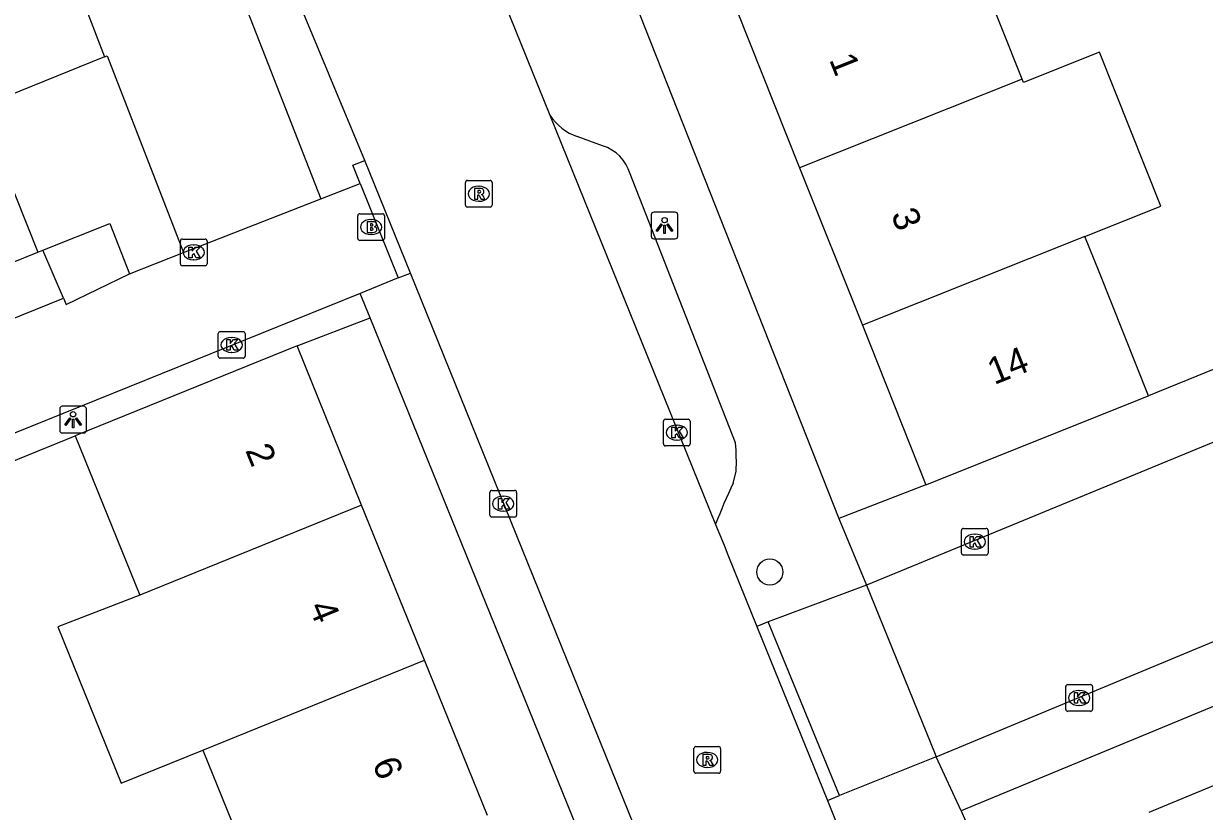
# Model space of a CAD drawing. Extents: x 162990 to 165007, y 383433 to 384336.
# Drawn here: x 163858.48 to 163902.75, y 383900.1 to 383929.63 of the extents above; entities that cross this region are included whole.
import ezdxf

# ---------------------------------------------------------------- set-up
doc = ezdxf.new("R2010")
doc.units = 0
for name, color, linetype in [('IMGEO_Boom', 7, 'Continuous'), ('IMGEO_Brandkraan', 7, 'Continuous'), ('IMGEO_Kolk', 7, 'Continuous'), ('IMGEO_Lichtpunt', 7, 'Continuous'), ('IMGEO_Pand', 7, 'Continuous'), ('IMGEO_Pand_nummerreeks', 7, 'Continuous'), ('IMGEO_Rijbaan_lokaal_open', 7, 'Continuous'), ('IMGEO_Rioolput', 7, 'Continuous'), ('IMGEO_Voetpad_open', 7, 'Continuous')]:
    doc.layers.add(name, color=color, linetype=linetype)

msp = doc.modelspace()

# ---------------------------------------------------------------- linework, layer by layer
at = {"layer": 'IMGEO_Boom'}
msp.add_circle((163886.457, 383909.07), 0.489, dxfattribs=at)
at = {"layer": 'IMGEO_Brandkraan'}
for p, q in [((163871.01, 383921.575), (163871.01, 383922.427)), ((163871.085, 383922.501), (163871.937, 383922.501)), ((163871.498, 383922.281), (163871.523, 383922.281)), ((163872.011, 383922.427), (163872.011, 383921.575)), ((163871.521, 383921.721), (163871.496, 383921.721)), ((163871.937, 383921.501), (163871.085, 383921.501))]:
    msp.add_line(p, q, dxfattribs=at)
for points in [[(163871.01, 383921.575), (163871.01, 383922.427)], [(163871.085, 383922.501), (163871.937, 383922.501)], [(163871.358, 383922.201), (163871.358, 383921.801), (163871.571, 383921.801)], [(163871.589, 383922.201), (163871.358, 383922.201)], [(163872.011, 383922.427), (163872.011, 383921.575)], [(163871.537, 383922.12), (163871.483, 383922.12), (163871.483, 383922.044)], [(163871.483, 383922.044), (163871.536, 383922.044)], [(163871.545, 383921.968), (163871.483, 383921.968), (163871.483, 383921.887)], [(163871.483, 383921.887), (163871.545, 383921.887)], [(163871.937, 383921.501), (163871.085, 383921.501)]]:
    msp.add_lwpolyline(points, dxfattribs=at)
for centre, radius, start, end in [((163871.087, 383922.425), 0.0765, 91.552, 178.448), ((163871.087, 383922.425), 0.0765, 91.552, 178.448), ((163871.593, 383922.056), 0.145, 59.4692, 91.5367), ((163871.618, 383922.103), 0.0922, 285.5137, 58.1501), ((163871.935, 383922.425), 0.0765, 1.552, 88.448), ((163871.935, 383922.425), 0.0765, 1.552, 88.448), ((163871.538, 383922.082), 0.0379, 267.8285, 90.9355), ((163871.546, 383921.927), 0.0404, 269.8759, 90.5077), ((163871.577, 383922.052), 0.251, 268.6676, 293.5347), ((163871.623, 383921.911), 0.105, 301.3115, 78.989), ((163871.087, 383921.577), 0.0765, 181.552, 268.448), ((163871.087, 383921.577), 0.0765, 181.552, 268.448), ((163871.935, 383921.577), 0.0765, 271.552, 358.448), ((163871.935, 383921.577), 0.0765, 271.552, 358.448)]:
    msp.add_arc(centre, radius, start, end, dxfattribs=at)
for centre, major_axis, ratio, start_param, end_param in [((163871.497, 383922.001), (-0.387, 0.002), 0.722429, 4.712389, 7.853982), ((163871.522, 383922.001), (-0.39, 0.002), 0.717154, 1.570796, 4.712389)]:
    msp.add_ellipse(centre, major_axis=major_axis, ratio=ratio, start_param=start_param, end_param=end_param, dxfattribs=at)
at = {"layer": 'IMGEO_Kolk'}
for p, q in [((163864.359, 383920.625), (163864.359, 383921.477)), ((163864.434, 383921.551), (163865.286, 383921.551)), ((163864.847, 383921.331), (163864.872, 383921.331)), ((163865.36, 383921.477), (163865.36, 383920.625)), ((163865.286, 383920.551), (163864.434, 383920.551)), ((163864.87, 383920.771), (163864.845, 383920.771)), ((163865.782, 383917.158), (163865.782, 383918.01)), ((163865.857, 383918.084), (163866.709, 383918.084)), ((163866.27, 383917.864), (163866.295, 383917.864)), ((163866.783, 383918.01), (163866.783, 383917.158)), ((163866.293, 383917.304), (163866.268, 383917.304)), ((163866.709, 383917.084), (163865.857, 383917.084)), ((163882.468, 383913.872), (163882.468, 383914.724)), ((163882.543, 383914.798), (163883.395, 383914.798)), ((163883.469, 383914.724), (163883.469, 383913.872)), ((163882.956, 383914.578), (163882.981, 383914.578)), ((163883.395, 383913.798), (163882.543, 383913.798)), ((163882.979, 383914.018), (163882.954, 383914.018)), ((163875.963, 383911.203), (163875.963, 383912.055)), ((163876.038, 383912.129), (163876.89, 383912.129)), ((163876.964, 383912.055), (163876.964, 383911.203)), ((163876.451, 383911.909), (163876.476, 383911.909)), ((163876.89, 383911.129), (163876.038, 383911.129)), ((163876.474, 383911.349), (163876.449, 383911.349)), ((163893.64, 383909.779), (163893.64, 383910.631)), ((163893.715, 383910.705), (163894.567, 383910.705)), ((163894.641, 383910.631), (163894.641, 383909.779)), ((163894.128, 383910.485), (163894.153, 383910.485)), ((163894.151, 383909.925), (163894.126, 383909.925)), ((163894.567, 383909.705), (163893.715, 383909.705)), ((163897.552, 383903.921), (163897.552, 383904.773)), ((163897.627, 383904.847), (163898.479, 383904.847)), ((163898.04, 383904.627), (163898.065, 383904.627)), ((163898.553, 383904.773), (163898.553, 383903.921)), ((163898.063, 383904.067), (163898.038, 383904.067)), ((163898.479, 383903.847), (163897.627, 383903.847))]:
    msp.add_line(p, q, dxfattribs=at)
for points in [[(163864.359, 383920.625), (163864.359, 383921.477)], [(163864.434, 383921.551), (163865.286, 383921.551)], [(163864.68, 383921.251), (163864.803, 383921.251), (163864.803, 383921.1), (163864.933, 383921.251), (163865.097, 383921.251), (163864.951, 383921.1), (163865.104, 383920.851), (163864.952, 383920.851), (163864.867, 383921.015), (163864.803, 383920.948), (163864.803, 383920.851), (163864.68, 383920.851), (163864.68, 383921.251)], [(163865.36, 383921.477), (163865.36, 383920.625)], [(163865.286, 383920.551), (163864.434, 383920.551)], [(163865.782, 383917.158), (163865.782, 383918.01)], [(163865.857, 383918.084), (163866.709, 383918.084)], [(163866.103, 383917.784), (163866.226, 383917.784), (163866.226, 383917.633), (163866.356, 383917.784), (163866.52, 383917.784), (163866.374, 383917.633), (163866.527, 383917.384), (163866.375, 383917.384), (163866.29, 383917.548), (163866.226, 383917.481), (163866.226, 383917.384), (163866.103, 383917.384), (163866.103, 383917.784)], [(163866.783, 383918.01), (163866.783, 383917.158)], [(163866.709, 383917.084), (163865.857, 383917.084)], [(163882.468, 383913.872), (163882.468, 383914.724)], [(163882.543, 383914.798), (163883.395, 383914.798)], [(163883.469, 383914.724), (163883.469, 383913.872)], [(163882.789, 383914.498), (163882.912, 383914.498), (163882.912, 383914.347), (163883.042, 383914.498), (163883.206, 383914.498), (163883.06, 383914.347), (163883.213, 383914.098), (163883.061, 383914.098), (163882.976, 383914.262), (163882.912, 383914.195), (163882.912, 383914.098), (163882.789, 383914.098), (163882.789, 383914.498)], [(163883.395, 383913.798), (163882.543, 383913.798)], [(163875.963, 383911.203), (163875.963, 383912.055)], [(163876.038, 383912.129), (163876.89, 383912.129)], [(163876.964, 383912.055), (163876.964, 383911.203)], [(163876.284, 383911.829), (163876.407, 383911.829), (163876.407, 383911.678), (163876.537, 383911.829), (163876.701, 383911.829), (163876.555, 383911.678), (163876.708, 383911.429), (163876.556, 383911.429), (163876.471, 383911.593), (163876.407, 383911.526), (163876.407, 383911.429), (163876.284, 383911.429), (163876.284, 383911.829)], [(163876.89, 383911.129), (163876.038, 383911.129)], [(163893.64, 383909.779), (163893.64, 383910.631)], [(163893.715, 383910.705), (163894.567, 383910.705)], [(163894.641, 383910.631), (163894.641, 383909.779)], [(163893.961, 383910.405), (163894.084, 383910.405), (163894.084, 383910.254), (163894.214, 383910.405), (163894.378, 383910.405), (163894.232, 383910.254), (163894.385, 383910.005), (163894.233, 383910.005), (163894.148, 383910.169), (163894.084, 383910.102), (163894.084, 383910.005), (163893.961, 383910.005), (163893.961, 383910.405)], [(163894.567, 383909.705), (163893.715, 383909.705)], [(163897.552, 383903.921), (163897.552, 383904.773)], [(163897.627, 383904.847), (163898.479, 383904.847)], [(163897.873, 383904.547), (163897.996, 383904.547), (163897.996, 383904.396), (163898.126, 383904.547), (163898.29, 383904.547), (163898.144, 383904.396), (163898.297, 383904.147), (163898.145, 383904.147), (163898.06, 383904.311), (163897.996, 383904.244), (163897.996, 383904.147), (163897.873, 383904.147), (163897.873, 383904.547)], [(163898.553, 383904.773), (163898.553, 383903.921)], [(163898.479, 383903.847), (163897.627, 383903.847)]]:
    msp.add_lwpolyline(points, dxfattribs=at)
for centre, start, end in [((163864.436, 383921.475), 91.552, 178.448), ((163864.436, 383921.475), 91.552, 178.448), ((163865.284, 383921.475), 1.552, 88.448), ((163865.284, 383921.475), 1.552, 88.448), ((163864.436, 383920.627), 181.552, 268.448), ((163864.436, 383920.627), 181.552, 268.448), ((163865.284, 383920.627), 271.552, 358.448), ((163865.284, 383920.627), 271.552, 358.448), ((163865.859, 383918.008), 91.552, 178.448), ((163865.859, 383918.008), 91.552, 178.448), ((163866.707, 383918.008), 1.552, 88.448), ((163866.707, 383918.008), 1.552, 88.448), ((163865.859, 383917.16), 181.552, 268.448), ((163865.859, 383917.16), 181.552, 268.448), ((163866.707, 383917.16), 271.552, 358.448), ((163866.707, 383917.16), 271.552, 358.448), ((163882.545, 383914.722), 91.552, 178.448), ((163882.545, 383914.722), 91.552, 178.448), ((163883.393, 383914.722), 1.552, 88.448), ((163883.393, 383914.722), 1.552, 88.448), ((163882.545, 383913.874), 181.552, 268.448), ((163882.545, 383913.874), 181.552, 268.448), ((163883.393, 383913.874), 271.552, 358.448), ((163883.393, 383913.874), 271.552, 358.448), ((163876.04, 383912.053), 91.552, 178.448), ((163876.04, 383912.053), 91.552, 178.448), ((163876.888, 383912.053), 1.552, 88.448), ((163876.888, 383912.053), 1.552, 88.448), ((163876.04, 383911.205), 181.552, 268.448), ((163876.04, 383911.205), 181.552, 268.448), ((163876.888, 383911.205), 271.552, 358.448), ((163876.888, 383911.205), 271.552, 358.448), ((163893.717, 383910.629), 91.552, 178.448), ((163893.717, 383910.629), 91.552, 178.448), ((163894.565, 383910.629), 1.552, 88.448), ((163894.565, 383910.629), 1.552, 88.448), ((163893.717, 383909.781), 181.552, 268.448), ((163893.717, 383909.781), 181.552, 268.448), ((163894.565, 383909.781), 271.552, 358.448), ((163894.565, 383909.781), 271.552, 358.448), ((163897.629, 383904.771), 91.552, 178.448), ((163897.629, 383904.771), 91.552, 178.448), ((163898.477, 383904.771), 1.552, 88.448), ((163898.477, 383904.771), 1.552, 88.448), ((163897.629, 383903.923), 181.552, 268.448), ((163897.629, 383903.923), 181.552, 268.448), ((163898.477, 383903.923), 271.552, 358.448), ((163898.477, 383903.923), 271.552, 358.448)]:
    msp.add_arc(centre, 0.0765, start, end, dxfattribs=at)
for centre, major_axis, ratio, start_param, end_param in [((163864.846, 383921.051), (-0.387, 0.002), 0.722429, 4.712389, 7.853982), ((163864.871, 383921.051), (-0.39, 0.002), 0.717154, 1.570796, 4.712389), ((163866.269, 383917.584), (-0.387, 0.002), 0.722429, 4.712389, 7.853982), ((163866.294, 383917.584), (-0.39, 0.002), 0.717154, 1.570796, 4.712389), ((163882.955, 383914.298), (-0.387, 0.002), 0.722429, 4.712389, 7.853982), ((163882.98, 383914.298), (-0.39, 0.002), 0.717154, 1.570796, 4.712389), ((163876.45, 383911.629), (-0.387, 0.002), 0.722429, 4.712389, 7.853982), ((163876.475, 383911.629), (-0.39, 0.002), 0.717154, 1.570796, 4.712389), ((163894.127, 383910.205), (-0.387, 0.002), 0.722429, 4.712389, 7.853982), ((163894.152, 383910.205), (-0.39, 0.002), 0.717154, 1.570796, 4.712389), ((163898.039, 383904.347), (-0.387, 0.002), 0.722429, 4.712389, 7.853982), ((163898.064, 383904.347), (-0.39, 0.002), 0.717154, 1.570796, 4.712389)]:
    msp.add_ellipse(centre, major_axis=major_axis, ratio=ratio, start_param=start_param, end_param=end_param, dxfattribs=at)
at = {"layer": 'IMGEO_Lichtpunt'}
for p, q in [((163882.012, 383922.462), (163882.012, 383921.655)), ((163882.012, 383922.462), (163882.012, 383921.655)), ((163882.914, 383922.557), (163882.106, 383922.557)), ((163882.914, 383922.557), (163882.106, 383922.557)), ((163883.008, 383921.655), (163883.008, 383922.462)), ((163883.008, 383921.655), (163883.008, 383922.462)), ((163882.106, 383921.561), (163882.914, 383921.561)), ((163882.106, 383921.561), (163882.914, 383921.561)), ((163859.839, 383915.187), (163859.839, 383914.38)), ((163859.839, 383915.187), (163859.839, 383914.38)), ((163860.741, 383915.282), (163859.933, 383915.282)), ((163860.741, 383915.282), (163859.933, 383915.282)), ((163860.835, 383914.38), (163860.835, 383915.187)), ((163860.835, 383914.38), (163860.835, 383915.187)), ((163859.933, 383914.286), (163860.741, 383914.286)), ((163859.933, 383914.286), (163860.741, 383914.286))]:
    msp.add_line(p, q, dxfattribs=at)
for points in [[(163882.386, 383922.126), (163882.425, 383922.098), (163882.237, 383921.836), (163882.199, 383921.863), (163882.386, 383922.126)], [(163882.598, 383922.098), (163882.636, 383922.125), (163882.823, 383921.863), (163882.784, 383921.835), (163882.598, 383922.098)], [(163882.488, 383922.078), (163882.535, 383922.078), (163882.535, 383921.756), (163882.488, 383921.756), (163882.488, 383922.078)], [(163860.213, 383914.851), (163860.252, 383914.823), (163860.064, 383914.561), (163860.026, 383914.588), (163860.213, 383914.851)], [(163860.315, 383914.803), (163860.362, 383914.803), (163860.362, 383914.481), (163860.315, 383914.481), (163860.315, 383914.803)], [(163860.425, 383914.823), (163860.463, 383914.85), (163860.65, 383914.588), (163860.611, 383914.56), (163860.425, 383914.823)]]:
    msp.add_lwpolyline(points, dxfattribs=at)
for centre in [(163882.511, 383922.26), (163860.338, 383914.985)]:
    msp.add_circle(centre, 0.0994, dxfattribs=at)
for centre, start, end in [((163882.106, 383922.462), 90, 180), ((163882.106, 383922.462), 90, 180), ((163882.914, 383922.462), 0, 90), ((163882.914, 383922.462), 0, 90), ((163882.106, 383921.655), 180, 270), ((163882.106, 383921.655), 180, 270), ((163882.914, 383921.655), 270, 0), ((163882.914, 383921.655), 270, 360), ((163859.933, 383915.187), 90, 180), ((163859.933, 383915.187), 90, 180), ((163860.741, 383915.187), 0, 90), ((163860.741, 383915.187), 0, 90), ((163859.933, 383914.38), 180, 270), ((163859.933, 383914.38), 180, 270), ((163860.741, 383914.38), 270, 0), ((163860.741, 383914.38), 270, 360)]:
    msp.add_arc(centre, 0.0946, start, end, dxfattribs=at)
at = {"layer": 'IMGEO_Pand'}
for points in [[(163895.92, 383927.552), (163893.554, 383933.487), (163889.854, 383932.012), (163885.209, 383930.159), (163887.575, 383924.225)], [(163865.994, 383932.372), (163860.862, 383930.368), (163860.76, 383930.328), (163861.518, 383928.387)], [(163865.994, 383932.372), (163869.631, 383923.057)], [(163861.518, 383928.387), (163857.008, 383926.563), (163856.839, 383926.494)], [(163861.518, 383928.387), (163861.615, 383928.426), (163864.475, 383921.044)], [(163898.271, 383921.653), (163901.12, 383922.789), (163898.82, 383928.557), (163895.972, 383927.422), (163895.92, 383927.552)], [(163895.92, 383927.552), (163887.575, 383924.225)], [(163856.839, 383926.494), (163859.018, 383921.061)], [(163887.575, 383924.225), (163889.926, 383918.326)], [(163864.475, 383921.044), (163869.631, 383923.057)], [(163859.203, 383921.136), (163861.716, 383922.135), (163862.45, 383920.253)], [(163898.271, 383921.653), (163889.926, 383918.326)], [(163900.656, 383915.672), (163898.804, 383920.317), (163898.271, 383921.653)], [(163854.065, 383919.058), (163859.018, 383921.061)], [(163859.018, 383921.061), (163859.203, 383921.136)], [(163862.45, 383920.253), (163864.475, 383921.044)], [(163889.926, 383918.326), (163892.311, 383912.344)], [(163868.735, 383917.547), (163860.42, 383914.175)], [(163871.155, 383911.579), (163868.735, 383917.547)], [(163892.311, 383912.344), (163900.656, 383915.672)], [(163860.42, 383914.175), (163862.841, 383908.207)], [(163871.155, 383911.579), (163862.841, 383908.207)], [(163873.515, 383905.76), (163871.155, 383911.579)], [(163862.841, 383908.207), (163859.762, 383907.015), (163862.142, 383901.149), (163865.2, 383902.389)], [(163865.2, 383902.389), (163873.515, 383905.76)], [(163875.875, 383899.94), (163873.515, 383905.76)], [(163865.2, 383902.389), (163867.561, 383896.568)], [(163900.679, 383900.072), (163906.5, 383902.482)]]:
    msp.add_lwpolyline(points, dxfattribs=at)
at = {"layer": 'IMGEO_Rijbaan_lokaal_open'}
for points in [[(163867.535, 383952.578), (163878.213, 383926.2)], [(163871.275, 383924.498), (163860.765, 383949.747)], [(163892.691, 383902.14), (163982.692, 383939.577)], [(163878.213, 383926.2), (163884.425, 383910.857)], [(163872.984, 383920.278), (163871.275, 383924.498)], [(163869.631, 383923.057), (163871.094, 383923.633)], [(163871.094, 383923.633), (163872.52, 383920.092)], [(163859.978, 383919.33), (163860.077, 383919.099), (163862.45, 383920.253)], [(163872.52, 383920.092), (163871.097, 383919.517)], [(163883.249, 383894.937), (163872.984, 383920.278)], [(163871.097, 383919.517), (163840.163, 383907.009), (163839.605, 383906.788)], [(163805.517, 383897.306), (163859.978, 383919.33)], [(163912.068, 383917.637), (163890.075, 383908.575)], [(163884.425, 383910.857), (163884.739, 383910.081), (163884.885, 383909.709), (163885.975, 383907.029)], [(163890.075, 383908.575), (163892.626, 383902.3), (163892.691, 383902.14)], [(163885.975, 383907.029), (163888.615, 383900.508)], [(163888.615, 383900.508), (163889.385, 383898.605)]]:
    msp.add_lwpolyline(points, dxfattribs=at)
at = {"layer": 'IMGEO_Rioolput'}
for p, q in [((163875.045, 383922.823), (163875.045, 383923.675)), ((163875.12, 383923.749), (163875.972, 383923.749)), ((163875.533, 383923.529), (163875.558, 383923.529)), ((163876.046, 383923.675), (163876.046, 383922.823)), ((163875.972, 383922.749), (163875.12, 383922.749)), ((163875.556, 383922.969), (163875.531, 383922.969)), ((163883.611, 383901.601), (163883.611, 383902.453)), ((163883.686, 383902.527), (163884.538, 383902.527)), ((163884.099, 383902.307), (163884.124, 383902.307)), ((163884.612, 383902.453), (163884.612, 383901.601)), ((163884.538, 383901.527), (163883.686, 383901.527)), ((163884.122, 383901.747), (163884.097, 383901.747))]:
    msp.add_line(p, q, dxfattribs=at)
for points in [[(163875.045, 383922.823), (163875.045, 383923.675)], [(163875.12, 383923.749), (163875.972, 383923.749)], [(163876.046, 383923.675), (163876.046, 383922.823)], [(163875.634, 383923.447), (163875.382, 383923.449), (163875.382, 383923.049)], [(163875.382, 383923.049), (163875.506, 383923.049), (163875.506, 383923.211), (163875.517, 383923.211)], [(163875.56, 383923.368), (163875.506, 383923.368), (163875.506, 383923.287)], [(163875.506, 383923.287), (163875.558, 383923.287)], [(163875.564, 383923.182), (163875.635, 383923.049), (163875.775, 383923.049), (163875.71, 383923.175)], [(163875.972, 383922.749), (163875.12, 383922.749)], [(163883.611, 383901.601), (163883.611, 383902.453)], [(163883.686, 383902.527), (163884.538, 383902.527)], [(163884.2, 383902.225), (163883.948, 383902.227), (163883.948, 383901.827)], [(163884.612, 383902.453), (163884.612, 383901.601)], [(163883.948, 383901.827), (163884.072, 383901.827), (163884.072, 383901.989), (163884.083, 383901.989)], [(163884.126, 383902.146), (163884.072, 383902.146), (163884.072, 383902.065)], [(163884.072, 383902.065), (163884.124, 383902.065)], [(163884.13, 383901.96), (163884.201, 383901.827), (163884.341, 383901.827), (163884.276, 383901.953)], [(163884.538, 383901.527), (163883.686, 383901.527)]]:
    msp.add_lwpolyline(points, dxfattribs=at)
for centre, radius, start, end in [((163875.122, 383923.673), 0.0765, 91.552, 178.448), ((163875.122, 383923.673), 0.0765, 91.552, 178.448), ((163875.97, 383923.673), 0.0765, 1.552, 88.448), ((163875.97, 383923.673), 0.0765, 1.552, 88.448), ((163875.516, 383923.158), 0.0533, 26.0293, 88.6989), ((163875.542, 383923.476), 0.19, 274.7715, 282.9687), ((163875.566, 383923.272), 0.0964, 77.0061, 93.1865), ((163875.58, 383923.329), 0.0378, 276.6634, 79.6772), ((163875.633, 383923.337), 0.109, 350.3612, 89.416), ((163875.631, 383923.337), 0.112, 277.5842, 350.9817), ((163875.615, 383923.122), 0.108, 29.5134, 73.7905), ((163875.122, 383922.825), 0.0765, 181.552, 268.448), ((163875.122, 383922.825), 0.0765, 181.552, 268.448), ((163875.97, 383922.825), 0.0765, 271.552, 358.448), ((163875.97, 383922.825), 0.0765, 271.552, 358.448), ((163883.688, 383902.451), 0.0765, 91.552, 178.448), ((163883.688, 383902.451), 0.0765, 91.552, 178.448), ((163884.199, 383902.115), 0.109, 350.3612, 89.416), ((163884.536, 383902.451), 0.0765, 1.552, 88.448), ((163884.536, 383902.451), 0.0765, 1.552, 88.448), ((163884.082, 383901.936), 0.0533, 26.0293, 88.6989), ((163884.108, 383902.254), 0.19, 274.7715, 282.9687), ((163884.132, 383902.05), 0.0964, 77.0061, 93.1865), ((163884.146, 383902.107), 0.0378, 276.6634, 79.6772), ((163884.197, 383902.115), 0.112, 277.5842, 350.9817), ((163884.181, 383901.9), 0.108, 29.5134, 73.7905), ((163883.688, 383901.603), 0.0765, 181.552, 268.448), ((163883.688, 383901.603), 0.0765, 181.552, 268.448), ((163884.536, 383901.603), 0.0765, 271.552, 358.448), ((163884.536, 383901.603), 0.0765, 271.552, 358.448)]:
    msp.add_arc(centre, radius, start, end, dxfattribs=at)
for centre, major_axis, ratio, start_param, end_param in [((163875.532, 383923.249), (-0.387, 0.002), 0.722429, 4.712389, 7.853982), ((163875.557, 383923.249), (-0.39, 0.002), 0.717154, 1.570796, 4.712389), ((163884.098, 383902.027), (-0.387, 0.002), 0.722429, 4.712389, 7.853982), ((163884.123, 383902.027), (-0.39, 0.002), 0.717154, 1.570796, 4.712389)]:
    msp.add_ellipse(centre, major_axis=major_axis, ratio=ratio, start_param=start_param, end_param=end_param, dxfattribs=at)
at = {"layer": 'IMGEO_Voetpad_open'}
for points in [[(163881.179, 383930.988), (163889.038, 383911.071)], [(163964.512, 383929.456), (163893.635, 383900.12)], [(163880.188, 383925.052), (163879.235, 383925.391)], [(163871.094, 383923.633), (163870.819, 383924.317), (163871.275, 383924.498)], [(163885.166, 383913.911), (163881.22, 383924.002)], [(163859.978, 383919.33), (163859.203, 383921.136)], [(163872.52, 383920.092), (163872.984, 383920.278)], [(163871.479, 383918.594), (163871.097, 383919.517)], [(163910.782, 383919.794), (163900.656, 383915.672)], [(163868.735, 383917.547), (163871.479, 383918.594)], [(163881.409, 383894.107), (163871.479, 383918.594)], [(163851.928, 383910.731), (163860.42, 383914.175)], [(163885.078, 383912.4), (163885.192, 383912.838)], [(163892.311, 383912.344), (163889.038, 383911.071)], [(163889.038, 383911.071), (163890.075, 383908.575)], [(163890.075, 383908.575), (163886.39, 383907.198)], [(163886.39, 383907.198), (163885.975, 383907.029)], [(163889.067, 383900.692), (163886.39, 383907.198)], [(163892.691, 383902.14), (163889.067, 383900.692)], [(163893.635, 383900.12), (163892.691, 383902.14)], [(163888.615, 383900.508), (163889.067, 383900.692)], [(163893.635, 383900.12), (163894.721, 383897.605)]]:
    msp.add_lwpolyline(points, dxfattribs=at)
for centre, radius, start, end in [((163879.913, 383927.297), 2.023, 212.8444, 250.4263), ((163879.692, 383923.533), 1.598, 17.0808, 71.9285), ((163878.798, 383913.22), 6.405, 356.5818, 6.1943), ((163906.029, 383902.624), 23.12, 154.9853, 159.1384)]:
    msp.add_arc(centre, radius, start, end, dxfattribs=at)

# ---------------------------------------------------------------- texts
at = {"layer": 'IMGEO_Pand_nummerreeks'}
for s, rotation, p in [('1', 291.7348, (163888.669, 383928.285)), ('3', 291.7348, (163890.986, 383922.474)), ('14', 21.7422, (163894.867, 383916.077)), ('2', 292.0737, (163866.782, 383913.637)), ('4', 292.0737, (163869.162, 383907.766)), ('6', 292.0737, (163871.542, 383901.896))]:
    msp.add_text(s, height=1, rotation=rotation, dxfattribs=at).set_placement(p)

doc.saveas('drawing.dxf')
